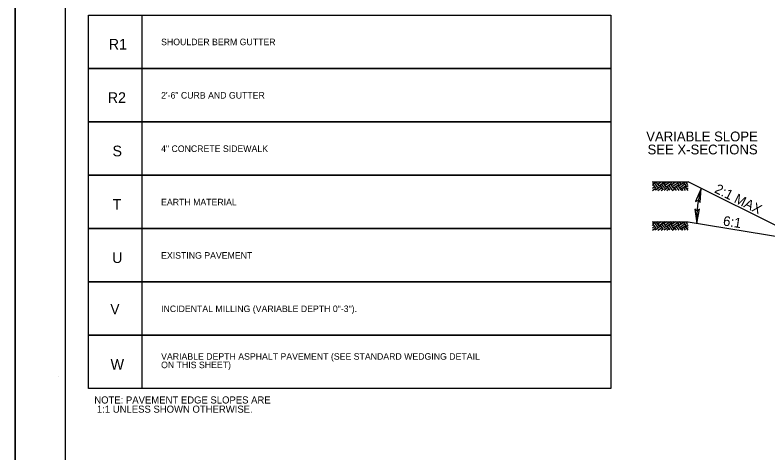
# Model space of a CAD drawing. Extents: x 1184121 to 1184397, y 1246506 to 1246661.
# Drawn here: x 1184121.1 to 1184197.8, y 1246550.4 to 1246595 of the extents above; entities that cross this region are included whole.
import ezdxf

# ---------------------------------------------------------------- set-up
doc = ezdxf.new("R2010")
doc.units = 0
for name, color, linetype in [('Sheet Data Field CELL', 7, 'Continuous'), ('Sheet Plan CELL', 7, 'Continuous'), ('Sheet Plot Border Outside CELL', 7, 'Continuous'), ('z - Construction', 7, 'Continuous')]:
    doc.layers.add(name, color=color, linetype=linetype)

msp = doc.modelspace()

# ---------------------------------------------------------------- linework, layer by layer
at = {"layer": 'Sheet Data Field CELL'}
for p, q in [((1184185.975, 1246577.999), (1184189.629, 1246577.999)), ((1184185.975, 1246577.999), (1184189.629, 1246577.999)), ((1184185.989, 1246577.787), (1184186.285, 1246577.999)), ((1184185.989, 1246577.787), (1184186.285, 1246577.999)), ((1184185.989, 1246577.624), (1184186.044, 1246577.663)), ((1184185.989, 1246577.624), (1184186.044, 1246577.663)), ((1184185.989, 1246577.38), (1184186.16, 1246577.502)), ((1184185.989, 1246577.38), (1184186.16, 1246577.502)), ((1184186.368, 1246577.326), (1184186.059, 1246577.756)), ((1184186.368, 1246577.326), (1184186.059, 1246577.756)), ((1184186.529, 1246577.442), (1184186.22, 1246577.872)), ((1184186.529, 1246577.442), (1184186.22, 1246577.872)), ((1184186.353, 1246577.234), (1184186.782, 1246577.543)), ((1184186.353, 1246577.234), (1184186.782, 1246577.543)), ((1184186.69, 1246577.558), (1184186.381, 1246577.987)), ((1184186.69, 1246577.558), (1184186.381, 1246577.987)), ((1184186.474, 1246577.972), (1184186.512, 1246578)), ((1184186.474, 1246577.972), (1184186.512, 1246578)), ((1184186.541, 1246577.124), (1184186.898, 1246577.381)), ((1184186.541, 1246577.124), (1184186.898, 1246577.381)), ((1184186.589, 1246577.811), (1184186.854, 1246578.001)), ((1184186.589, 1246577.811), (1184186.854, 1246578.001)), ((1184186.705, 1246577.65), (1184187.135, 1246577.959)), ((1184186.705, 1246577.65), (1184187.135, 1246577.959)), ((1184187.106, 1246577.205), (1184186.798, 1246577.635)), ((1184187.106, 1246577.205), (1184186.798, 1246577.635)), ((1184187.267, 1246577.321), (1184186.959, 1246577.751)), ((1184187.267, 1246577.321), (1184186.959, 1246577.751)), ((1184187.429, 1246577.437), (1184187.12, 1246577.866)), ((1184187.429, 1246577.437), (1184187.12, 1246577.866)), ((1184187.168, 1246577.168), (1184187.521, 1246577.422)), ((1184187.168, 1246577.168), (1184187.521, 1246577.422)), ((1184187.227, 1246577.944), (1184187.185, 1246578.002)), ((1184187.227, 1246577.944), (1184187.185, 1246578.002)), ((1184187.212, 1246577.851), (1184187.423, 1246578.003)), ((1184187.212, 1246577.851), (1184187.423, 1246578.003)), ((1184187.328, 1246577.69), (1184187.758, 1246577.999)), ((1184187.328, 1246577.69), (1184187.758, 1246577.999)), ((1184187.444, 1246577.529), (1184187.873, 1246577.838)), ((1184187.444, 1246577.529), (1184187.873, 1246577.838)), ((1184187.794, 1246577.156), (1184187.536, 1246577.514)), ((1184187.794, 1246577.156), (1184187.536, 1246577.514)), ((1184188.006, 1246577.2), (1184187.697, 1246577.63)), ((1184188.006, 1246577.2), (1184187.697, 1246577.63)), ((1184187.966, 1246577.823), (1184187.835, 1246578.004)), ((1184187.966, 1246577.823), (1184187.835, 1246578.004)), ((1184188.167, 1246577.316), (1184187.858, 1246577.746)), ((1184188.167, 1246577.316), (1184187.858, 1246577.746)), ((1184187.951, 1246577.73), (1184188.333, 1246578.005)), ((1184187.951, 1246577.73), (1184188.333, 1246578.005)), ((1184188.066, 1246577.569), (1184188.496, 1246577.878)), ((1184188.066, 1246577.569), (1184188.496, 1246577.878)), ((1184188.127, 1246577.939), (1184188.079, 1246578.005)), ((1184188.127, 1246577.939), (1184188.079, 1246578.005)), ((1184188.182, 1246577.408), (1184188.612, 1246577.717)), ((1184188.182, 1246577.408), (1184188.612, 1246577.717)), ((1184188.455, 1246577.142), (1184188.274, 1246577.393)), ((1184188.455, 1246577.142), (1184188.274, 1246577.393)), ((1184188.703, 1246577.137), (1184188.436, 1246577.509)), ((1184188.703, 1246577.137), (1184188.436, 1246577.509)), ((1184188.704, 1246577.702), (1184188.491, 1246577.999)), ((1184188.704, 1246577.702), (1184188.491, 1246577.999)), ((1184188.905, 1246577.195), (1184188.597, 1246577.625)), ((1184188.905, 1246577.195), (1184188.597, 1246577.625)), ((1184188.689, 1246577.61), (1184189.119, 1246577.918)), ((1184188.689, 1246577.61), (1184189.119, 1246577.918)), ((1184188.865, 1246577.818), (1184188.729, 1246578.006)), ((1184188.865, 1246577.818), (1184188.729, 1246578.006)), ((1184188.805, 1246577.448), (1184189.234, 1246577.757)), ((1184188.805, 1246577.448), (1184189.234, 1246577.757)), ((1184188.921, 1246577.287), (1184189.35, 1246577.596)), ((1184188.921, 1246577.287), (1184189.35, 1246577.596)), ((1184189.026, 1246577.933), (1184188.979, 1246577.999)), ((1184189.026, 1246577.933), (1184188.979, 1246577.999)), ((1184189.442, 1246577.581), (1184189.142, 1246577.999)), ((1184189.442, 1246577.581), (1184189.142, 1246577.999)), ((1184189.364, 1246577.124), (1184189.174, 1246577.388)), ((1184189.364, 1246577.124), (1184189.174, 1246577.388)), ((1184189.612, 1246577.119), (1184189.335, 1246577.504)), ((1184189.612, 1246577.119), (1184189.335, 1246577.504)), ((1184189.604, 1246577.697), (1184189.387, 1246577.999)), ((1184189.604, 1246577.697), (1184189.387, 1246577.999)), ((1184189.427, 1246577.489), (1184189.629, 1246577.634)), ((1184189.427, 1246577.489), (1184189.629, 1246577.634)), ((1184189.543, 1246577.328), (1184189.629, 1246577.39)), ((1184189.543, 1246577.328), (1184189.629, 1246577.39)), ((1184201.787, 1246571.92), (1184189.629, 1246577.999)), ((1184185.989, 1246577.136), (1184186.276, 1246577.341)), ((1184185.989, 1246577.136), (1184186.276, 1246577.341)), ((1184186.35, 1246577.124), (1184186.261, 1246577.249)), ((1184186.35, 1246577.124), (1184186.261, 1246577.249)), ((1184186.881, 1246577.124), (1184187.014, 1246577.22)), ((1184186.881, 1246577.124), (1184187.014, 1246577.22)), ((1184187.447, 1246577.124), (1184187.637, 1246577.261)), ((1184187.447, 1246577.124), (1184187.637, 1246577.261)), ((1184188.014, 1246577.124), (1184188.259, 1246577.301)), ((1184188.014, 1246577.124), (1184188.259, 1246577.301)), ((1184188.932, 1246577.133), (1184188.998, 1246577.18)), ((1184188.932, 1246577.133), (1184188.998, 1246577.18)), ((1184189.116, 1246577.129), (1184189.013, 1246577.272)), ((1184189.116, 1246577.129), (1184189.013, 1246577.272)), ((1184185.975, 1246573.946), (1184189.629, 1246573.946)), ((1184185.975, 1246573.946), (1184189.629, 1246573.946)), ((1184185.989, 1246573.735), (1184186.285, 1246573.947)), ((1184185.989, 1246573.735), (1184186.285, 1246573.947)), ((1184185.989, 1246573.572), (1184186.044, 1246573.611)), ((1184185.989, 1246573.572), (1184186.044, 1246573.611)), ((1184186.368, 1246573.274), (1184186.059, 1246573.703)), ((1184186.368, 1246573.274), (1184186.059, 1246573.703)), ((1184186.529, 1246573.389), (1184186.22, 1246573.819)), ((1184186.529, 1246573.389), (1184186.22, 1246573.819)), ((1184186.69, 1246573.505), (1184186.381, 1246573.935)), ((1184186.69, 1246573.505), (1184186.381, 1246573.935)), ((1184186.474, 1246573.92), (1184186.512, 1246573.948)), ((1184186.474, 1246573.92), (1184186.512, 1246573.948)), ((1184186.589, 1246573.759), (1184186.854, 1246573.949)), ((1184186.589, 1246573.759), (1184186.854, 1246573.949)), ((1184186.705, 1246573.598), (1184187.135, 1246573.906)), ((1184186.705, 1246573.598), (1184187.135, 1246573.906)), ((1184187.106, 1246573.153), (1184186.798, 1246573.582)), ((1184187.106, 1246573.153), (1184186.798, 1246573.582)), ((1184187.267, 1246573.269), (1184186.959, 1246573.698)), ((1184187.267, 1246573.269), (1184186.959, 1246573.698)), ((1184187.429, 1246573.384), (1184187.12, 1246573.814)), ((1184187.429, 1246573.384), (1184187.12, 1246573.814)), ((1184187.227, 1246573.891), (1184187.185, 1246573.95)), ((1184187.227, 1246573.891), (1184187.185, 1246573.95)), ((1184187.212, 1246573.799), (1184187.423, 1246573.95)), ((1184187.212, 1246573.799), (1184187.423, 1246573.95)), ((1184187.328, 1246573.638), (1184187.758, 1246573.947)), ((1184187.328, 1246573.638), (1184187.758, 1246573.947)), ((1184187.444, 1246573.477), (1184187.873, 1246573.785)), ((1184187.444, 1246573.477), (1184187.873, 1246573.785)), ((1184188.006, 1246573.148), (1184187.697, 1246573.577)), ((1184188.006, 1246573.148), (1184187.697, 1246573.577)), ((1184187.966, 1246573.77), (1184187.835, 1246573.951)), ((1184187.966, 1246573.77), (1184187.835, 1246573.951)), ((1184188.167, 1246573.263), (1184187.858, 1246573.693)), ((1184188.167, 1246573.263), (1184187.858, 1246573.693)), ((1184187.951, 1246573.678), (1184188.333, 1246573.953)), ((1184187.951, 1246573.678), (1184188.333, 1246573.953)), ((1184188.066, 1246573.517), (1184188.496, 1246573.826)), ((1184188.066, 1246573.517), (1184188.496, 1246573.826)), ((1184188.127, 1246573.886), (1184188.079, 1246573.952)), ((1184188.127, 1246573.886), (1184188.079, 1246573.952)), ((1184188.182, 1246573.356), (1184188.612, 1246573.665)), ((1184188.182, 1246573.356), (1184188.612, 1246573.665)), ((1184188.704, 1246573.649), (1184188.491, 1246573.946)), ((1184188.704, 1246573.649), (1184188.491, 1246573.946)), ((1184188.905, 1246573.143), (1184188.597, 1246573.572)), ((1184188.905, 1246573.143), (1184188.597, 1246573.572)), ((1184188.689, 1246573.557), (1184189.119, 1246573.866)), ((1184188.689, 1246573.557), (1184189.119, 1246573.866)), ((1184188.865, 1246573.765), (1184188.729, 1246573.954)), ((1184188.865, 1246573.765), (1184188.729, 1246573.954)), ((1184188.805, 1246573.396), (1184189.234, 1246573.705)), ((1184188.805, 1246573.396), (1184189.234, 1246573.705)), ((1184188.921, 1246573.235), (1184189.35, 1246573.544)), ((1184188.921, 1246573.235), (1184189.35, 1246573.544)), ((1184189.026, 1246573.881), (1184188.979, 1246573.946)), ((1184189.026, 1246573.881), (1184188.979, 1246573.946)), ((1184189.442, 1246573.529), (1184189.142, 1246573.946)), ((1184189.442, 1246573.529), (1184189.142, 1246573.946)), ((1184189.604, 1246573.644), (1184189.387, 1246573.946)), ((1184189.604, 1246573.644), (1184189.387, 1246573.946)), ((1184189.427, 1246573.436), (1184189.629, 1246573.581)), ((1184189.427, 1246573.436), (1184189.629, 1246573.581)), ((1184189.629, 1246573.946), (1184201.787, 1246571.92)), ((1184185.989, 1246573.327), (1184186.16, 1246573.45)), ((1184185.989, 1246573.327), (1184186.16, 1246573.45)), ((1184185.989, 1246573.083), (1184186.276, 1246573.289)), ((1184185.989, 1246573.083), (1184186.276, 1246573.289)), ((1184186.35, 1246573.072), (1184186.261, 1246573.196)), ((1184186.35, 1246573.072), (1184186.261, 1246573.196)), ((1184186.353, 1246573.181), (1184186.782, 1246573.49)), ((1184186.353, 1246573.181), (1184186.782, 1246573.49)), ((1184186.541, 1246573.072), (1184186.898, 1246573.329)), ((1184186.541, 1246573.072), (1184186.898, 1246573.329)), ((1184186.881, 1246573.072), (1184187.014, 1246573.168)), ((1184186.881, 1246573.072), (1184187.014, 1246573.168)), ((1184187.168, 1246573.116), (1184187.521, 1246573.369)), ((1184187.168, 1246573.116), (1184187.521, 1246573.369)), ((1184187.447, 1246573.072), (1184187.637, 1246573.208)), ((1184187.447, 1246573.072), (1184187.637, 1246573.208)), ((1184187.794, 1246573.103), (1184187.536, 1246573.462)), ((1184187.794, 1246573.103), (1184187.536, 1246573.462)), ((1184188.014, 1246573.072), (1184188.259, 1246573.248)), ((1184188.014, 1246573.072), (1184188.259, 1246573.248)), ((1184188.455, 1246573.09), (1184188.274, 1246573.341)), ((1184188.455, 1246573.09), (1184188.274, 1246573.341)), ((1184188.703, 1246573.085), (1184188.436, 1246573.456)), ((1184188.703, 1246573.085), (1184188.436, 1246573.456)), ((1184188.932, 1246573.08), (1184188.998, 1246573.127)), ((1184188.932, 1246573.08), (1184188.998, 1246573.127)), ((1184189.116, 1246573.077), (1184189.013, 1246573.22)), ((1184189.116, 1246573.077), (1184189.013, 1246573.22)), ((1184189.364, 1246573.072), (1184189.174, 1246573.336)), ((1184189.364, 1246573.072), (1184189.174, 1246573.336)), ((1184189.612, 1246573.067), (1184189.335, 1246573.451)), ((1184189.612, 1246573.067), (1184189.335, 1246573.451)), ((1184189.543, 1246573.275), (1184189.629, 1246573.337)), ((1184189.543, 1246573.275), (1184189.629, 1246573.337)), ((1184125.507, 1246558.153), (1184125.507, 1246558.153))]:
    msp.add_line(p, q, dxfattribs=at)
for points in [[(1184133.99, 1246589.575), (1184128.548, 1246589.575), (1184128.548, 1246595.017), (1184181.761, 1246595.017), (1184181.761, 1246589.575), (1184133.99, 1246589.575), (1184133.99, 1246595.017)], [(1184133.99, 1246584.133), (1184128.548, 1246584.133), (1184128.548, 1246589.575), (1184181.761, 1246589.575), (1184181.761, 1246584.133), (1184133.99, 1246584.133), (1184133.99, 1246589.575)], [(1184133.99, 1246578.691), (1184128.548, 1246578.691), (1184128.548, 1246584.133), (1184181.761, 1246584.133), (1184181.761, 1246578.691), (1184133.99, 1246578.691), (1184133.99, 1246584.133)], [(1184133.99, 1246573.249), (1184128.548, 1246573.249), (1184128.548, 1246578.691), (1184181.761, 1246578.691), (1184181.761, 1246573.249), (1184133.99, 1246573.249), (1184133.99, 1246578.691)], [(1184133.99, 1246567.806), (1184128.548, 1246567.806), (1184128.548, 1246573.249), (1184181.761, 1246573.249), (1184181.761, 1246567.806), (1184133.99, 1246567.806), (1184133.99, 1246573.249)], [(1184133.99, 1246562.364), (1184128.548, 1246562.364), (1184128.548, 1246567.806), (1184181.761, 1246567.806), (1184181.761, 1246562.364), (1184133.99, 1246562.364), (1184133.99, 1246567.806)], [(1184133.99, 1246556.922), (1184128.548, 1246556.922), (1184128.548, 1246562.364), (1184181.761, 1246562.364), (1184181.761, 1246556.922), (1184133.99, 1246556.922), (1184133.99, 1246562.364)]]:
    msp.add_lwpolyline(points, dxfattribs=at)
for points in [[(1184190.866, 1246575.917), (1184190.944, 1246577.342), (1184190.385, 1246576.019), (1184190.668, 1246576.139)], [(1184190.3, 1246575.211), (1184190.508, 1246573.8), (1184190.792, 1246575.207), (1184190.537, 1246575.034)]]:
    msp.add_lwpolyline(points, close=True, dxfattribs=at)
msp.add_arc((1184202.599, 1246574.11), 12.096, 164.50116, 181.46653, dxfattribs=at)
at = {"layer": 'Sheet Plan CELL'}
msp.add_line((1184126.181, 1246508.875), (1184126.184, 1246657.364), dxfattribs=at)
at = {"layer": 'Sheet Plot Border Outside CELL'}
msp.add_lwpolyline([(1184121.05, 1246660.53), (1184360.324, 1246660.53), (1184360.324, 1246505.708), (1184121.05, 1246505.708)], close=True, dxfattribs=at)
at = {"layer": 'z - Construction'}
msp.add_line((1184121.05, 1246660.53), (1184121.05, 1246505.708), dxfattribs=at)

# ---------------------------------------------------------------- texts
at = {"layer": 'Sheet Data Field CELL'}
for s, height, p in [('R1', 1.0864, (1184130.593, 1246591.498)), ('SHOULDER BERM GUTTER', 0.66516, (1184135.93, 1246591.941)), ('R2', 1.0864, (1184130.495, 1246586.056)), ('2\'-6" CURB AND GUTTER', 0.66516, (1184135.93, 1246586.498)), ('S', 1.086, (1184130.977, 1246580.614)), ('4" CONCRETE SIDEWALK', 0.66516, (1184135.93, 1246581.056)), ('T', 1.086, (1184130.995, 1246575.172)), ('EARTH MATERIAL', 0.66516, (1184135.93, 1246575.614)), ('U', 1.086, (1184130.943, 1246569.73)), ('EXISTING PAVEMENT', 0.66516, (1184135.93, 1246570.172)), ('V', 1.064, (1184130.752, 1246564.504)), ('INCIDENTAL MILLING (VARIABLE DEPTH 0"-3"). ', 0.66517, (1184135.93, 1246564.73)), ('VARIABLE DEPTH ASPHALT PAVEMENT (SEE STANDARD WEDGING DETAIL', 0.66516, (1184135.93, 1246559.87)), ('W', 1.086, (1184130.782, 1246558.846)), ('ON THIS SHEET)', 0.66516, (1184135.93, 1246559.009)), ('NOTE: PAVEMENT EDGE SLOPES ARE', 0.72391, (1184129.123, 1246555.405)), (' 1:1 UNLESS SHOWN OTHERWISE.', 0.72391, (1184129.123, 1246554.468))]:
    msp.add_text(s, height=height, dxfattribs=at).set_placement(p)
for s, rotation, p in [('VARIABLE SLOPE', 360, (1184185.354, 1246582.136)), ('SEE X-SECTIONS', 360, (1184185.487, 1246580.806)), ('2:1 MAX', 333.43475, (1184192.23, 1246576.96)), ('6:1', 351.39374, (1184193.133, 1246573.56))]:
    msp.add_text(s, height=1, rotation=rotation, dxfattribs=at).set_placement(p)

doc.saveas('drawing.dxf')
